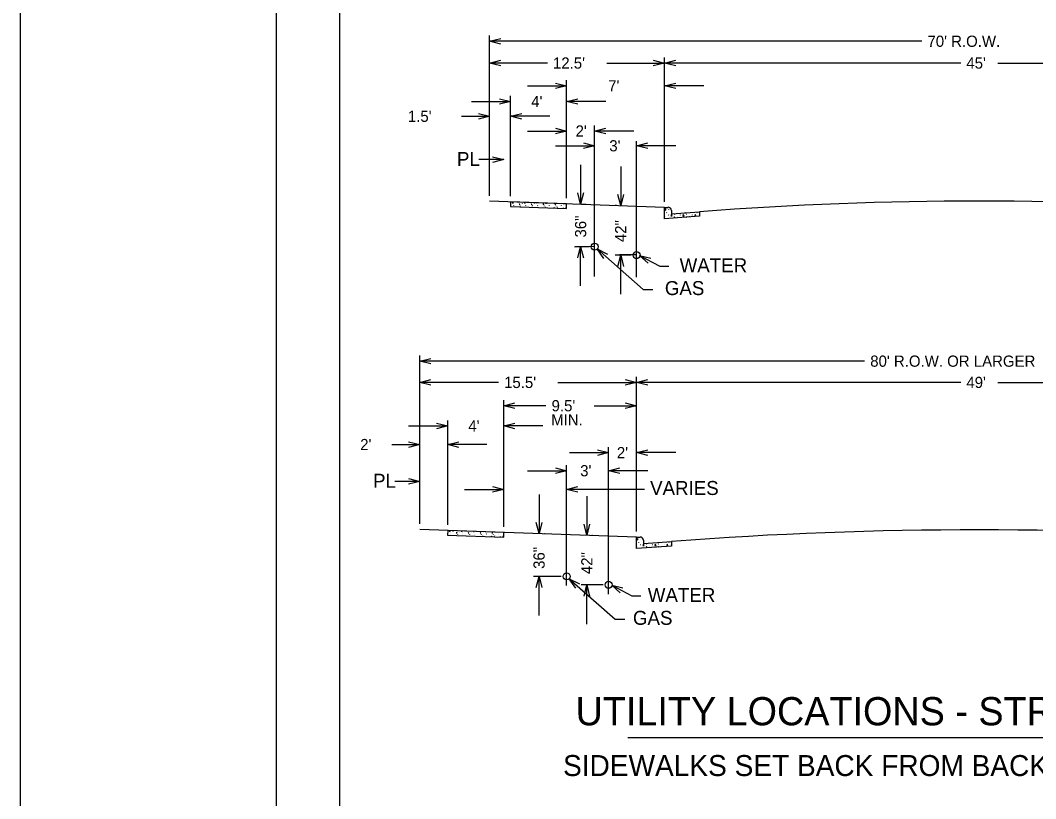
# Model space of a CAD drawing. Extents: x 524397 to 525117, y 3701341 to 3701821.
# Drawn here: x 524396.8 to 524541.9, y 3701603.7 to 3701715 of the extents above; entities that cross this region are included whole.
import ezdxf

# ---------------------------------------------------------------- set-up
doc = ezdxf.new("R2010")
doc.units = 0
for name, color, linetype in [('Level 1', 7, 'Continuous'), ('Level 11', 7, 'Continuous'), ('Level 9', 7, 'Continuous'), ('Pam batch print border', 7, 'Continuous')]:
    doc.layers.add(name, color=color, linetype=linetype)

msp = doc.modelspace()

# ---------------------------------------------------------------- linework, layer by layer
at = {"layer": 'Level 1'}
for p, q in [((524442.4, 3701790.98), (524442.4, 3701370.98)), ((524483.62, 3701612.51), (524573.02, 3701612.51))]:
    msp.add_line(p, q, dxfattribs=at)
at = {"layer": 'Level 11'}
for p, q in [((524463.87, 3701689.93), (524463.87, 3701712.8)), ((524525.66, 3701712), (524463.87, 3701712)), ((524463.87, 3701689.93), (524463.87, 3701709.69)), ((524472.13, 3701708.89), (524463.87, 3701708.89)), ((524480.61, 3701708.89), (524488.87, 3701708.89)), ((524488.87, 3701689.06), (524488.87, 3701709.69)), ((524531.22, 3701708.89), (524488.87, 3701708.89)), ((524536.52, 3701708.89), (524578.87, 3701708.89)), ((524469.28, 3701705.63), (524474.88, 3701705.63)), ((524473.28, 3701706.03), (524474.88, 3701705.63)), ((524474.88, 3701705.63), (524473.28, 3701705.23)), ((524474.88, 3701689.58), (524474.88, 3701706.43)), ((524488.87, 3701689.06), (524488.87, 3701706.43)), ((524488.87, 3701705.63), (524490.47, 3701706.03)), ((524488.87, 3701705.63), (524490.47, 3701706.03)), ((524494.47, 3701705.63), (524488.87, 3701705.63)), ((524490.47, 3701705.23), (524488.87, 3701705.63)), ((524490.47, 3701705.23), (524488.87, 3701705.63)), ((524466.88, 3701689.86), (524466.88, 3701704.19)), ((524474.88, 3701689.58), (524474.88, 3701704.19)), ((524461.28, 3701703.39), (524466.88, 3701703.39)), ((524465.28, 3701703.79), (524466.88, 3701703.39)), ((524466.88, 3701703.39), (524465.28, 3701702.99)), ((524474.88, 3701703.39), (524476.48, 3701703.79)), ((524480.48, 3701703.39), (524474.88, 3701703.39)), ((524476.48, 3701702.99), (524474.88, 3701703.39)), ((524459.87, 3701701.28), (524463.87, 3701701.28)), ((524462.27, 3701701.68), (524463.87, 3701701.28)), ((524463.87, 3701701.28), (524462.27, 3701700.88)), ((524463.87, 3701689.97), (524463.87, 3701702.08)), ((524466.88, 3701689.86), (524466.88, 3701702.08)), ((524466.88, 3701701.28), (524468.49, 3701701.68)), ((524472.49, 3701701.28), (524466.88, 3701701.28)), ((524468.49, 3701700.88), (524466.88, 3701701.28)), ((524478.88, 3701678.38), (524478.88, 3701699.95)), ((524469.28, 3701699.17), (524474.88, 3701699.17)), ((524473.28, 3701699.57), (524474.88, 3701699.17)), ((524474.88, 3701699.17), (524473.28, 3701698.77)), ((524478.88, 3701699.17), (524480.48, 3701699.57)), ((524484.48, 3701699.17), (524478.88, 3701699.17)), ((524480.48, 3701698.77), (524478.88, 3701699.17)), ((524473.28, 3701697.06), (524478.88, 3701697.06)), ((524477.28, 3701697.46), (524478.88, 3701697.06)), ((524478.88, 3701697.06), (524477.28, 3701696.66)), ((524484.88, 3701678.27), (524484.88, 3701697.71)), ((524484.88, 3701697.06), (524486.48, 3701697.46)), ((524490.48, 3701697.06), (524484.88, 3701697.06)), ((524486.48, 3701696.66), (524484.88, 3701697.06)), ((524464.28, 3701695.48), (524465.88, 3701695.08)), ((524465.88, 3701695.08), (524462.31, 3701695.08)), ((524465.88, 3701695.08), (524464.28, 3701694.68)), ((524476.88, 3701694.33), (524476.88, 3701688.73)), ((524482.61, 3701694.12), (524482.61, 3701688.52)), ((524476.88, 3701688.73), (524476.48, 3701690.33)), ((524477.28, 3701690.33), (524476.88, 3701688.73)), ((524482.61, 3701688.52), (524482.21, 3701690.12)), ((524483.01, 3701690.12), (524482.61, 3701688.52)), ((524488.87, 3701688.26), (524463.87, 3701689.13)), ((524466.88, 3701689.03), (524466.86, 3701688.37)), ((524466.86, 3701688.37), (524474.88, 3701688.09)), ((524474.88, 3701688.75), (524466.88, 3701689.03)), ((524467.35, 3701688.48), (524467.33, 3701688.52)), ((524467.67, 3701688.9), (524467.66, 3701688.93)), ((524468.27, 3701688.48), (524468.26, 3701688.45)), ((524468.29, 3701688.48), (524468.27, 3701688.46)), ((524468.53, 3701688.81), (524468.53, 3701688.77)), ((524469.05, 3701688.48), (524469.04, 3701688.52)), ((524469.37, 3701688.9), (524469.36, 3701688.93)), ((524469.97, 3701688.48), (524469.96, 3701688.45)), ((524469.99, 3701688.48), (524469.97, 3701688.46)), ((524470.23, 3701688.81), (524470.23, 3701688.77)), ((524470.75, 3701688.48), (524470.74, 3701688.52)), ((524471.68, 3701688.48), (524471.66, 3701688.45)), ((524471.69, 3701688.48), (524471.68, 3701688.46)), ((524471.9, 3701688.22), (524471.88, 3701688.25)), ((524471.93, 3701688.81), (524471.93, 3701688.77)), ((524472.45, 3701688.48), (524472.44, 3701688.52)), ((524472.73, 3701688.16), (524472.73, 3701688.17)), ((524473.38, 3701688.48), (524473.36, 3701688.45)), ((524473.39, 3701688.48), (524473.38, 3701688.46)), ((524473.6, 3701688.22), (524473.59, 3701688.25)), ((524473.63, 3701688.79), (524473.63, 3701688.77)), ((524474.15, 3701688.48), (524474.14, 3701688.52)), ((524474.44, 3701688.14), (524474.43, 3701688.17)), ((524474.88, 3701688.09), (524474.88, 3701688.75)), ((524477.12, 3701688.73), (524477.68, 3701688.73)), ((524482.01, 3701688.52), (524481.81, 3701688.52)), ((524488.87, 3701686.6), (524488.87, 3701688.26)), ((524488.87, 3701688.26), (524489.38, 3701688.26)), ((524489.38, 3701688.26), (524489.37, 3701688.26)), ((524493.87, 3701686.98), (524488.87, 3701686.6)), ((524489.03, 3701686.92), (524489.02, 3701686.9)), ((524489.19, 3701687.49), (524489.18, 3701687.52)), ((524489.48, 3701687.14), (524489.46, 3701687.18)), ((524489.51, 3701687.9), (524489.5, 3701687.93)), ((524489.87, 3701687.8), (524489.87, 3701687.34)), ((524489.87, 3701687.34), (524493.87, 3701687.64)), ((524490.34, 3701687.23), (524490.32, 3701687.26)), ((524490.74, 3701686.92), (524490.72, 3701686.9)), ((524491.18, 3701687.14), (524491.16, 3701687.18)), ((524491.81, 3701687.48), (524491.8, 3701687.46)), ((524491.83, 3701687.48), (524491.81, 3701687.47)), ((524492.04, 3701687.23), (524492.02, 3701687.26)), ((524492.44, 3701686.92), (524492.42, 3701686.9)), ((524492.59, 3701687.49), (524492.58, 3701687.52)), ((524492.88, 3701687.14), (524492.87, 3701687.18)), ((524493.52, 3701687.48), (524493.5, 3701687.46)), ((524493.53, 3701687.49), (524493.52, 3701687.47)), ((524493.74, 3701687.23), (524493.73, 3701687.26)), ((524493.87, 3701687.64), (524493.87, 3701686.98)), ((524478.88, 3701682.65), (524475.99, 3701682.59)), ((524478.08, 3701682.64), (524476.08, 3701682.64)), ((524476.48, 3701681.04), (524476.88, 3701682.64)), ((524476.88, 3701677.04), (524476.88, 3701682.64)), ((524476.88, 3701682.64), (524477.28, 3701681.04)), ((524480.19, 3701680.95), (524479.26, 3701682.31)), ((524479.26, 3701682.31), (524480.72, 3701681.55)), ((524479.26, 3701682.31), (524485.82, 3701676.53)), ((524484.08, 3701681.43), (524481.81, 3701681.43)), ((524482.21, 3701679.83), (524482.61, 3701681.43)), ((524482.43, 3701681.54), (524484.88, 3701681.54)), ((524482.61, 3701675.83), (524482.61, 3701681.43)), ((524482.61, 3701681.43), (524483.01, 3701679.83)), ((524486.54, 3701680.3), (524485.32, 3701681.4)), ((524485.32, 3701681.4), (524486.92, 3701681)), ((524485.32, 3701681.4), (524488.19, 3701679.87)), ((524488.19, 3701679.87), (524489.49, 3701679.87)), ((524485.82, 3701676.53), (524487.22, 3701676.53)), ((524453.89, 3701643.02), (524453.89, 3701667.08)), ((524453.89, 3701666.28), (524455.49, 3701666.68)), ((524517.48, 3701666.28), (524453.89, 3701666.28)), ((524455.49, 3701665.88), (524453.89, 3701666.28)), ((524453.89, 3701643.02), (524453.89, 3701664.04)), ((524453.89, 3701663.24), (524455.49, 3701663.64)), ((524483.27, 3701663.64), (524484.87, 3701663.24)), ((524484.87, 3701641.94), (524484.87, 3701664.04)), ((524484.87, 3701663.24), (524486.47, 3701663.64)), ((524465.14, 3701663.24), (524453.89, 3701663.24)), ((524455.49, 3701662.84), (524453.89, 3701663.24)), ((524473.62, 3701663.24), (524484.87, 3701663.24)), ((524484.87, 3701663.24), (524483.27, 3701662.84)), ((524531.22, 3701663.24), (524484.87, 3701663.24)), ((524486.47, 3701662.84), (524484.87, 3701663.24)), ((524536.52, 3701663.24), (524582.87, 3701663.24)), ((524465.88, 3701643.4), (524465.88, 3701660.71)), ((524484.87, 3701641.94), (524484.87, 3701660.71)), ((524465.88, 3701659.91), (524467.49, 3701660.31)), ((524471.93, 3701659.91), (524465.88, 3701659.91)), ((524467.49, 3701659.51), (524465.88, 3701659.91)), ((524478.83, 3701659.91), (524484.87, 3701659.91)), ((524483.27, 3701660.31), (524484.87, 3701659.91)), ((524484.87, 3701659.91), (524483.27, 3701659.51)), ((524457.89, 3701642.88), (524457.89, 3701657.82)), ((524465.88, 3701642.6), (524465.88, 3701657.82)), ((524452.29, 3701657.02), (524457.89, 3701657.02)), ((524456.29, 3701657.42), (524457.89, 3701657.02)), ((524457.89, 3701657.02), (524456.29, 3701656.62)), ((524465.88, 3701657.02), (524467.49, 3701657.42)), ((524471.49, 3701657.02), (524465.88, 3701657.02)), ((524467.49, 3701656.62), (524465.88, 3701657.02)), ((524452.29, 3701654.76), (524453.89, 3701654.36)), ((524453.89, 3701643.02), (524453.89, 3701655.16)), ((524457.89, 3701642.88), (524457.89, 3701655.16)), ((524457.89, 3701654.36), (524459.49, 3701654.76)), ((524449.89, 3701654.36), (524453.89, 3701654.36)), ((524453.89, 3701654.36), (524452.29, 3701653.96)), ((524463.49, 3701654.36), (524457.89, 3701654.36)), ((524459.49, 3701653.96), (524457.89, 3701654.36)), ((524479.28, 3701653.6), (524480.88, 3701653.2)), ((524480.88, 3701632.96), (524480.88, 3701654)), ((524480.88, 3701653.91), (524480.88, 3701654)), ((524484.87, 3701642.74), (524484.87, 3701654)), ((524484.87, 3701653.2), (524486.47, 3701653.6)), ((524475.28, 3701653.2), (524480.88, 3701653.2)), ((524480.88, 3701653.2), (524479.28, 3701652.8)), ((524490.47, 3701653.2), (524484.87, 3701653.2)), ((524486.47, 3701652.8), (524484.87, 3701653.2)), ((524469.28, 3701650.62), (524474.88, 3701650.62)), ((524473.28, 3701651.02), (524474.88, 3701650.62)), ((524474.88, 3701650.62), (524473.28, 3701650.22)), ((524474.88, 3701634.21), (524474.88, 3701651.42)), ((524474.88, 3701651.32), (524474.88, 3701651.42)), ((524480.88, 3701651.4), (524480.88, 3701651.42)), ((524480.88, 3701650.62), (524482.48, 3701651.02)), ((524486.48, 3701650.62), (524480.88, 3701650.62)), ((524482.48, 3701650.22), (524480.88, 3701650.62)), ((524453.89, 3701649.09), (524450.32, 3701649.09)), ((524452.29, 3701649.49), (524453.89, 3701649.09)), ((524453.89, 3701649.09), (524452.29, 3701648.69)), ((524460.28, 3701647.95), (524465.88, 3701647.95)), ((524464.28, 3701648.35), (524465.88, 3701647.95)), ((524465.88, 3701647.95), (524464.28, 3701647.55)), ((524465.88, 3701642.6), (524465.88, 3701648.75)), ((524474.88, 3701647.95), (524476.48, 3701648.35)), ((524486.01, 3701647.95), (524474.88, 3701647.95)), ((524476.48, 3701647.55), (524474.88, 3701647.95)), ((524470.94, 3701647.23), (524470.94, 3701641.63)), ((524474.88, 3701647.19), (524474.88, 3701647.15)), ((524477.77, 3701646.99), (524477.77, 3701641.39)), ((524470.94, 3701641.63), (524470.54, 3701643.23)), ((524471.34, 3701643.23), (524470.94, 3701641.63)), ((524484.87, 3701641.14), (524453.89, 3701642.22)), ((524457.89, 3701642.08), (524457.87, 3701641.42)), ((524465.88, 3701641.8), (524457.89, 3701642.08)), ((524458.68, 3701641.95), (524458.66, 3701641.98)), ((524459.53, 3701641.86), (524459.53, 3701641.83)), ((524460.38, 3701641.95), (524460.36, 3701641.98)), ((524461.24, 3701641.86), (524461.23, 3701641.83)), ((524462.94, 3701641.86), (524462.93, 3701641.83)), ((524464.64, 3701641.84), (524464.63, 3701641.83)), ((524465.88, 3701641.14), (524465.88, 3701641.8)), ((524471.65, 3701641.63), (524471.74, 3701641.63)), ((524477.77, 3701641.39), (524477.37, 3701642.99)), ((524478.17, 3701642.99), (524477.77, 3701641.39)), ((524457.87, 3701641.42), (524465.88, 3701641.14)), ((524458.35, 3701641.53), (524458.34, 3701641.57)), ((524459.28, 3701641.53), (524459.26, 3701641.51)), ((524459.29, 3701641.53), (524459.28, 3701641.51)), ((524460.05, 3701641.53), (524460.04, 3701641.57)), ((524460.98, 3701641.53), (524460.96, 3701641.51)), ((524460.99, 3701641.53), (524460.98, 3701641.51)), ((524461.76, 3701641.53), (524461.74, 3701641.57)), ((524462.68, 3701641.53), (524462.67, 3701641.51)), ((524462.69, 3701641.53), (524462.68, 3701641.51)), ((524462.9, 3701641.27), (524462.89, 3701641.3)), ((524463.46, 3701641.53), (524463.44, 3701641.57)), ((524463.73, 3701641.22), (524463.73, 3701641.22)), ((524464.38, 3701641.53), (524464.37, 3701641.51)), ((524464.4, 3701641.53), (524464.38, 3701641.51)), ((524464.61, 3701641.27), (524464.59, 3701641.3)), ((524465.16, 3701641.53), (524465.15, 3701641.57)), ((524465.45, 3701641.19), (524465.43, 3701641.22)), ((524478.48, 3701641.39), (524478.57, 3701641.39)), ((524484.87, 3701639.48), (524484.87, 3701641.14)), ((524484.87, 3701641.14), (524485.38, 3701641.14)), ((524485.19, 3701640.37), (524485.18, 3701640.4)), ((524485.38, 3701641.14), (524485.37, 3701641.14)), ((524485.51, 3701640.78), (524485.5, 3701640.81)), ((524485.87, 3701640.68), (524485.87, 3701640.21)), ((524485.87, 3701640.21), (524489.87, 3701640.51)), ((524487.81, 3701640.36), (524487.8, 3701640.34)), ((524487.83, 3701640.36), (524487.81, 3701640.35)), ((524488.59, 3701640.37), (524488.58, 3701640.4)), ((524489.52, 3701640.36), (524489.5, 3701640.34)), ((524489.53, 3701640.37), (524489.52, 3701640.35)), ((524489.87, 3701640.51), (524489.87, 3701639.85)), ((524489.87, 3701639.85), (524484.87, 3701639.48)), ((524485.03, 3701639.79), (524485.02, 3701639.77)), ((524485.48, 3701640.02), (524485.46, 3701640.05)), ((524486.34, 3701640.1), (524486.32, 3701640.14)), ((524486.74, 3701639.79), (524486.72, 3701639.77)), ((524487.18, 3701640.02), (524487.16, 3701640.05)), ((524488.04, 3701640.1), (524488.02, 3701640.14)), ((524488.44, 3701639.79), (524488.42, 3701639.77)), ((524488.88, 3701640.02), (524488.87, 3701640.05)), ((524489.74, 3701640.1), (524489.73, 3701640.14)), ((524474.08, 3701635.52), (524470.14, 3701635.52)), ((524470.54, 3701633.92), (524470.94, 3701635.52)), ((524470.94, 3701629.91), (524470.94, 3701635.52)), ((524470.94, 3701635.52), (524471.34, 3701633.92)), ((524476.19, 3701633.83), (524475.26, 3701635.19)), ((524475.26, 3701635.19), (524476.72, 3701634.43)), ((524475.26, 3701635.19), (524481.82, 3701629.4)), ((524480.08, 3701634.31), (524476.97, 3701634.31)), ((524477.37, 3701632.71), (524477.77, 3701634.31)), ((524477.77, 3701628.7), (524477.77, 3701634.31)), ((524477.77, 3701634.31), (524478.17, 3701632.71)), ((524482.54, 3701633.17), (524481.32, 3701634.28)), ((524481.32, 3701634.28), (524482.92, 3701633.88)), ((524481.32, 3701634.28), (524484.19, 3701632.75)), ((524484.19, 3701632.75), (524485.49, 3701632.75)), ((524481.82, 3701629.4), (524483.22, 3701629.4))]:
    msp.add_line(p, q, dxfattribs=at)
for points in [[(524465.47, 3701711.6), (524463.87, 3701712), (524465.47, 3701712.4)], [(524465.47, 3701708.49), (524463.87, 3701708.89), (524465.47, 3701709.29)], [(524487.27, 3701709.29), (524488.87, 3701708.89), (524487.27, 3701708.49)], [(524490.47, 3701708.49), (524488.87, 3701708.89), (524490.47, 3701709.29)], [(524467.17, 3701689.02), (524467.08, 3701688.93), (524467.24, 3701688.86)], [(524467.24, 3701688.86), (524467.22, 3701689.02)], [(524468.2, 3701688.67), (524468.16, 3701688.76), (524468.09, 3701688.7), (524468.2, 3701688.67)], [(524468.82, 3701688.96), (524468.79, 3701688.93), (524468.94, 3701688.86)], [(524468.94, 3701688.86), (524468.93, 3701688.96)], [(524469.91, 3701688.67), (524469.86, 3701688.76), (524469.79, 3701688.7), (524469.91, 3701688.67)], [(524470.55, 3701688.9), (524470.64, 3701688.86)], [(524470.64, 3701688.86), (524470.64, 3701688.9)], [(524471.43, 3701688.21), (524471.42, 3701688.22), (524471.42, 3701688.21)], [(524471.61, 3701688.67), (524471.56, 3701688.76), (524471.49, 3701688.7), (524471.61, 3701688.67)], [(524473.16, 3701688.15), (524473.12, 3701688.22), (524473.09, 3701688.15)], [(524473.31, 3701688.67), (524473.27, 3701688.76), (524473.2, 3701688.7), (524473.31, 3701688.67)], [(524474.88, 3701688.12), (524474.83, 3701688.22), (524474.77, 3701688.09)], [(524489.08, 3701687.86), (524489.05, 3701688.07), (524488.93, 3701687.94), (524489.08, 3701687.87)], [(524489.55, 3701686.65), (524489.54, 3701686.66), (524489.53, 3701686.65)], [(524489.96, 3701687.05), (524489.86, 3701687.23), (524489.79, 3701687.06), (524489.95, 3701687.05)], [(524490.36, 3701686.82), (524490.32, 3701686.91), (524490.25, 3701686.86), (524490.36, 3701686.82)], [(524491.66, 3701687.05), (524491.56, 3701687.23), (524491.49, 3701687.06), (524491.66, 3701687.05)], [(524492.06, 3701686.84), (524492.02, 3701686.91), (524491.95, 3701686.86), (524492.02, 3701686.84)], [(524493.36, 3701687.05), (524493.26, 3701687.23), (524493.19, 3701687.06), (524493.36, 3701687.05)], [(524458.17, 3701642.07), (524458.09, 3701641.98), (524458.24, 3701641.91)], [(524458.24, 3701641.91), (524458.22, 3701642.07)], [(524459.21, 3701641.72), (524459.17, 3701641.81), (524459.1, 3701641.76), (524459.21, 3701641.72)], [(524459.82, 3701642.01), (524459.79, 3701641.98), (524459.94, 3701641.91)], [(524459.95, 3701641.91), (524459.93, 3701642.01)], [(524460.91, 3701641.72), (524460.87, 3701641.81), (524460.8, 3701641.76), (524460.91, 3701641.72)], [(524461.56, 3701641.95), (524461.64, 3701641.91)], [(524461.65, 3701641.91), (524461.64, 3701641.95)], [(524462.61, 3701641.72), (524462.57, 3701641.81), (524462.5, 3701641.76), (524462.61, 3701641.72)], [(524464.31, 3701641.72), (524464.27, 3701641.81), (524464.2, 3701641.76), (524464.31, 3701641.72)], [(524462.44, 3701641.26), (524462.43, 3701641.28), (524462.42, 3701641.26)], [(524464.17, 3701641.2), (524464.13, 3701641.28), (524464.1, 3701641.2)], [(524465.88, 3701641.17), (524465.83, 3701641.28), (524465.77, 3701641.14)], [(524485.08, 3701640.74), (524485.05, 3701640.94), (524484.93, 3701640.81), (524485.08, 3701640.74)], [(524485.55, 3701639.53), (524485.54, 3701639.54), (524485.53, 3701639.53)], [(524485.96, 3701639.93), (524485.86, 3701640.11), (524485.79, 3701639.94), (524485.95, 3701639.93)], [(524486.36, 3701639.7), (524486.32, 3701639.79), (524486.25, 3701639.74), (524486.36, 3701639.7)], [(524487.66, 3701639.93), (524487.56, 3701640.11), (524487.49, 3701639.94), (524487.66, 3701639.93)], [(524488.06, 3701639.72), (524488.02, 3701639.79), (524487.95, 3701639.74), (524488.02, 3701639.71)], [(524489.36, 3701639.93), (524489.26, 3701640.11), (524489.19, 3701639.94), (524489.36, 3701639.93)]]:
    msp.add_lwpolyline(points, dxfattribs=at)
for centre in [(524478.88, 3701682.64), (524484.88, 3701681.43), (524474.88, 3701635.52), (524480.88, 3701634.31)]:
    msp.add_circle(centre, 0.5, dxfattribs=at)
for centre, radius, start, end in [((524489.38, 3701687.77), 0.494, 3.7079, 90.7668), ((524533.87, 3701157.84), 531.31, 85.6824, 94.3176), ((524533.87, 3701057.73), 584.44, 85.68236, 94.31764), ((524485.38, 3701640.64), 0.494, 3.7079, 90.7668)]:
    msp.add_arc(centre, radius, start, end, dxfattribs=at)
at = {"layer": 'Level 9'}
msp.add_lwpolyline([(524396.79, 3701820.98), (525116.79, 3701820.98), (525116.79, 3701340.98), (524396.79, 3701340.98)], close=True, dxfattribs=at)
at = {"layer": 'Pam batch print border'}
msp.add_lwpolyline([(524433.4, 3701796.98), (525105.4, 3701796.98), (525105.4, 3701364.98), (524433.4, 3701364.98)], close=True, dxfattribs=at)
msp.add_lwpolyline([(524433.4, 3701796.98), (525105.4, 3701796.98), (525105.4, 3701364.98), (524433.4, 3701364.98)], close=True, dxfattribs=at)

# ---------------------------------------------------------------- texts
at = {"layer": 'Level 1'}
msp.add_text('UTILITY LOCATIONS - STREET', height=4.0362, dxfattribs=at).set_placement((524476.16, 3701614.23))
at = {"layer": 'Level 11'}
for s, height, p in [("70' R.O.W.", 1.601, (524526.46, 3701711.2)), ("12.5'", 1.601, (524472.93, 3701708.09)), ("45'", 1.601, (524532.02, 3701708.09)), ("7'", 1.601, (524480.82, 3701704.83)), ("4'", 1.601, (524469.82, 3701702.59)), ("1.5'", 1.601, (524452.19, 3701700.48)), ("2'", 1.601, (524476.16, 3701698.37)), ("3'", 1.601, (524480.98, 3701696.26)), ('PL', 2, (524459.2, 3701694.17)), ('WATER', 2, (524491.03, 3701678.98)), ('GAS', 2, (524488.92, 3701675.72)), ("80' R.O.W. OR LARGER", 1.601, (524518.28, 3701665.48)), ("15.5'", 1.601, (524465.94, 3701662.44)), ("49'", 1.601, (524532.02, 3701662.44)), ("9.5'", 1.601, (524472.73, 3701659.11)), ("4'", 1.601, (524460.83, 3701656.22)), ('MIN.', 1.601, (524472.67, 3701657.09)), ("2'", 1.601, (524445.37, 3701653.56)), ("2'", 1.601, (524482.06, 3701652.4)), ("3'", 1.601, (524476.82, 3701649.82)), ('PL', 2, (524447.21, 3701648.18)), ('VARIES', 2, (524486.81, 3701647.15)), ('WATER', 2, (524486.48, 3701631.86)), ('GAS', 2, (524484.36, 3701628.59)), ('SIDEWALKS SET BACK FROM BACK-OF-CURB', 3, (524474.37, 3701606.98))]:
    msp.add_text(s, height=height, dxfattribs=at).set_placement(p)
for s, p in [('36"', (524477.68, 3701683.95)), ('42"', (524483.41, 3701683.29)), ('36"', (524471.74, 3701636.59)), ('42"', (524478.57, 3701635.84))]:
    msp.add_text(s, height=1.601, rotation=90, dxfattribs=at).set_placement(p)

doc.saveas('drawing.dxf')
